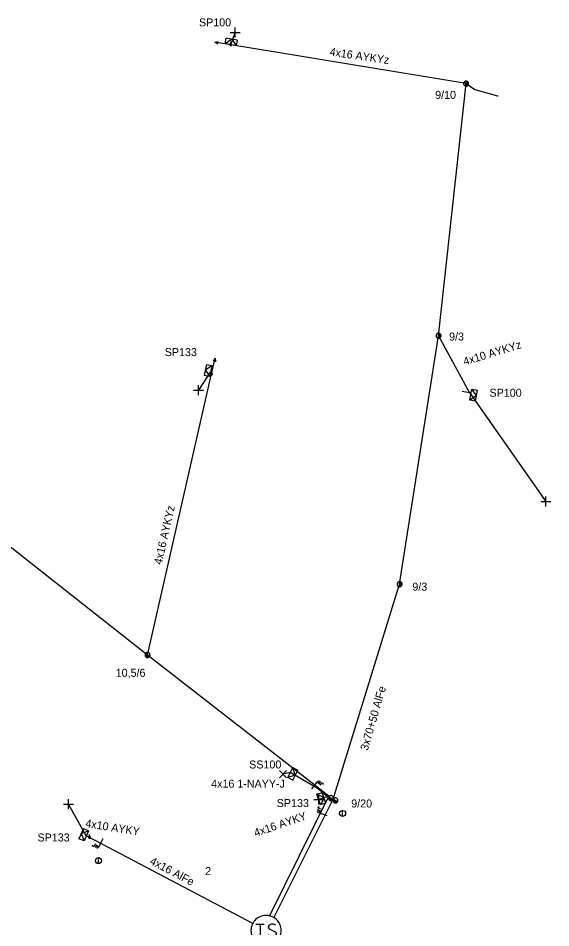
# Model space of a CAD drawing. Extents: x -717562 to -713845, y -1151196 to -1143903.
# Drawn here: x -717097.5 to -717030.9, y -1144017.1 to -1143903.4 of the extents above; entities that cross this region are included whole.
import ezdxf

# ---------------------------------------------------------------- set-up
doc = ezdxf.new("R2010")
doc.units = 0
for name, color, linetype in [('Vrstva 1', 7, 'Continuous'), ('Vrstva 10', 7, 'Continuous'), ('Vrstva 12', 7, 'Continuous'), ('Vrstva 13', 7, 'Continuous'), ('Vrstva 15', 7, 'Continuous'), ('Vrstva 18', 7, 'Continuous'), ('Vrstva 2', 7, 'Continuous'), ('Vrstva 25', 7, 'Continuous'), ('Vrstva 27', 7, 'Continuous'), ('Vrstva 31', 7, 'Continuous'), ('Vrstva 33', 7, 'Continuous'), ('Vrstva 34', 7, 'Continuous'), ('Vrstva 36', 7, 'Continuous'), ('Vrstva 52', 7, 'Continuous'), ('Vrstva 54', 7, 'Continuous'), ('Vrstva 55', 7, 'Continuous'), ('Vrstva 59', 7, 'Continuous'), ('Vrstva 6', 7, 'Continuous'), ('Vrstva 9', 7, 'Continuous')]:
    doc.layers.add(name, color=color, linetype=linetype)

# ---------------------------------------------------------------- blocks, each defined once
blk = doc.blocks.new('NN440')
at = {"layer": 'Vrstva 2'}
for points in [[(0.63, 0), (0.63, 0.06), (0.62, 0.13), (0.6, 0.19), (0.58, 0.25), (0.55, 0.31), (0.51, 0.37), (0.47, 0.42), (0.42, 0.46), (0.37, 0.51), (0.32, 0.54), (0.26, 0.57), (0.2, 0.59), (0.13, 0.61), (0.07, 0.62), (0, 0.63), (-0.06, 0.62), (-0.13, 0.61), (-0.19, 0.59), (-0.26, 0.57), (-0.31, 0.54), (-0.37, 0.51), (-0.42, 0.46), (-0.47, 0.42), (-0.51, 0.37), (-0.54, 0.31), (-0.57, 0.25), (-0.6, 0.19), (-0.62, 0.13), (-0.63, 0.06), (-0.63, 0), (-0.63, -0.07), (-0.62, -0.14), (-0.6, -0.2), (-0.57, -0.26), (-0.54, -0.32), (-0.51, -0.37), (-0.47, -0.43), (-0.42, -0.47), (-0.37, -0.51), (-0.31, -0.55), (-0.26, -0.58), (-0.19, -0.6), (-0.13, -0.62), (-0.06, -0.63), (0, -0.63), (0.07, -0.63), (0.13, -0.62), (0.2, -0.6), (0.26, -0.58), (0.32, -0.55), (0.37, -0.51), (0.42, -0.47), (0.47, -0.43), (0.51, -0.37), (0.55, -0.32), (0.58, -0.26), (0.6, -0.2), (0.62, -0.14), (0.63, -0.07), (0.63, 0)], [(-0.63, 0), (0.63, 0)], [(-0.6, -0.18), (0.57, -0.18)], [(-0.51, -0.32), (0.5, -0.32)], [(-0.37, -0.47), (0.35, -0.47)]]:
    blk.add_lwpolyline(points, dxfattribs=at)
blk = doc.blocks.new('NN450')
at = {"layer": 'Vrstva 2'}
for points in [[(0, 0), (0, 0.07), (-0.01, 0.13), (-0.03, 0.19), (-0.05, 0.25), (-0.08, 0.31), (-0.12, 0.37), (-0.16, 0.42), (-0.21, 0.46), (-0.26, 0.51), (-0.31, 0.54), (-0.37, 0.57), (-0.43, 0.59), (-0.5, 0.61), (-0.56, 0.62), (-0.63, 0.62), (-0.69, 0.62), (-0.75, 0.61), (-0.82, 0.59), (-0.88, 0.57), (-0.94, 0.54), (-0.99, 0.51), (-1.04, 0.46), (-1.09, 0.42), (-1.13, 0.37), (-1.17, 0.31), (-1.2, 0.25), (-1.22, 0.19), (-1.24, 0.13), (-1.25, 0.07), (-1.25, 0), (-1.25, -0.07), (-1.24, -0.13), (-1.22, -0.19), (-1.2, -0.25), (-1.17, -0.31), (-1.13, -0.37), (-1.09, -0.42), (-1.04, -0.46), (-0.99, -0.51), (-0.94, -0.54), (-0.88, -0.57), (-0.82, -0.59), (-0.75, -0.61), (-0.69, -0.62), (-0.62, -0.63), (-0.56, -0.62), (-0.5, -0.61), (-0.43, -0.59), (-0.37, -0.57), (-0.31, -0.54), (-0.26, -0.51), (-0.21, -0.46), (-0.16, -0.42), (-0.12, -0.37), (-0.08, -0.31), (-0.05, -0.25), (-0.03, -0.19), (-0.01, -0.13), (0, -0.07), (0, 0)], [(1.25, 0), (1.25, 0.07), (1.24, 0.13), (1.22, 0.19), (1.2, 0.25), (1.17, 0.31), (1.13, 0.37), (1.09, 0.42), (1.04, 0.46), (0.99, 0.51), (0.94, 0.54), (0.88, 0.57), (0.82, 0.59), (0.75, 0.61), (0.69, 0.62), (0.62, 0.62), (0.56, 0.62), (0.5, 0.61), (0.43, 0.59), (0.37, 0.57), (0.31, 0.54), (0.26, 0.51), (0.21, 0.46), (0.16, 0.42), (0.12, 0.37), (0.08, 0.31), (0.05, 0.25), (0.03, 0.19), (0.01, 0.13), (0, 0.07), (0, 0), (0, -0.07), (0.01, -0.13), (0.03, -0.19), (0.05, -0.25), (0.08, -0.31), (0.12, -0.37), (0.16, -0.42), (0.21, -0.46), (0.26, -0.51), (0.31, -0.54), (0.37, -0.57), (0.43, -0.59), (0.5, -0.61), (0.56, -0.62), (0.63, -0.63), (0.69, -0.62), (0.75, -0.61), (0.82, -0.59), (0.88, -0.57), (0.94, -0.54), (0.99, -0.51), (1.04, -0.46), (1.09, -0.42), (1.13, -0.37), (1.17, -0.31), (1.2, -0.25), (1.22, -0.19), (1.24, -0.13), (1.25, -0.07), (1.25, 0)], [(-1.25, 0), (1.25, 0)], [(-1.23, -0.16), (-0.02, -0.16)], [(-1.16, -0.32), (-0.09, -0.32)], [(-1.03, -0.47), (-0.22, -0.47)], [(0.02, -0.16), (1.23, -0.16)], [(0.09, -0.32), (1.16, -0.32)], [(0.22, -0.47), (1.03, -0.47)]]:
    blk.add_lwpolyline(points, dxfattribs=at)
blk = doc.blocks.new('NN560')
at = {"layer": 'Vrstva 2'}
for points in [[(2, 0), (1.59, 0.14)], [(0, 0), (2, 0)], [(2, 0), (1.59, -0.13)]]:
    blk.add_lwpolyline(points, dxfattribs=at)
blk = doc.blocks.new('NN840')
at = {"layer": 'Vrstva 15'}
for points in [[(0, 0.62), (0, -0.63)], [(-0.75, -0.71), (-0.75, -0.66)], [(-0.73, -0.76), (-0.75, -0.71)], [(-0.66, -0.8), (-0.73, -0.76)], [(-0.63, -0.8), (-0.66, -0.8)], [(-0.56, -0.76), (-0.63, -0.8)], [(-0.54, -0.71), (-0.56, -0.76)], [(-0.54, -0.38), (-0.54, -0.71)], [(-0.33, -0.38), (-0.33, -0.8)], [(-0.33, -0.64), (-0.13, -0.38)], [(-0.26, -0.56), (-0.09, -0.8)]]:
    blk.add_lwpolyline(points, dxfattribs=at)
blk = doc.blocks.new('NN770')
at = {"layer": 'Vrstva 10'}
for p, q in [((0, 0.19), (0, 0.26)), ((0, -0.28), (0, 0.11))]:
    blk.add_line(p, q, dxfattribs=at)
blk.add_circle((0, -0.01), 0.375, dxfattribs=at)
blk = doc.blocks.new('NN800')
at = {"layer": 'Vrstva 1'}
for points in [[(-0.44, 0.44), (0.44, -0.44)], [(-0.44, -0.44), (0.44, 0.44)]]:
    blk.add_lwpolyline(points, dxfattribs=at)
blk = doc.blocks.new('NN630')
at = {"layer": 'Vrstva 9'}
for points in [[(0, -0.7), (-0.7, 0)], [(-0.7, -0.7), (-0.7, 0), (0.7, 0), (0.7, -0.7)], [(-0.7, -0.7), (0.7, -0.7)], [(0, -0.7), (0.7, 0)]]:
    blk.add_lwpolyline(points, dxfattribs=at)
blk = doc.blocks.new('NN500')
at = {"layer": 'Vrstva 2'}
for points in [[(0, -0.24), (0.02, -0.23), (0.05, -0.23), (0.07, -0.22), (0.09, -0.22), (0.12, -0.2), (0.14, -0.19), (0.16, -0.18), (0.17, -0.16), (0.19, -0.14), (0.2, -0.12), (0.21, -0.1), (0.22, -0.07), (0.23, -0.05), (0.23, -0.02), (0.23, 0), (0.23, 0.02), (0.23, 0.05), (0.22, 0.07), (0.21, 0.1), (0.2, 0.12), (0.19, 0.14), (0.17, 0.16), (0.16, 0.17), (0.14, 0.19), (0.12, 0.2), (0.09, 0.21), (0.07, 0.22), (0.05, 0.23), (0.02, 0.23), (0, 0.23), (-0.03, 0.23), (-0.05, 0.23), (-0.07, 0.22), (-0.1, 0.21), (-0.12, 0.2), (-0.14, 0.19), (-0.16, 0.17), (-0.18, 0.16), (-0.19, 0.14), (-0.2, 0.12), (-0.22, 0.1), (-0.22, 0.07), (-0.23, 0.05), (-0.23, 0.02), (-0.24, 0), (-0.23, -0.02), (-0.23, -0.05), (-0.22, -0.07), (-0.22, -0.1), (-0.2, -0.12), (-0.19, -0.14), (-0.18, -0.16), (-0.16, -0.18), (-0.14, -0.19), (-0.12, -0.2), (-0.1, -0.22), (-0.07, -0.22), (-0.05, -0.23), (-0.03, -0.23), (0, -0.24)], [(0, -0.24), (0.02, -0.23), (0.05, -0.23), (0.07, -0.22), (0.09, -0.22), (0.12, -0.2), (0.14, -0.19), (0.16, -0.18), (0.17, -0.16), (0.19, -0.14), (0.2, -0.12), (0.21, -0.1), (0.22, -0.07), (0.23, -0.05), (0.23, -0.02), (0.23, 0), (0.23, 0.02), (0.23, 0.05), (0.22, 0.07), (0.21, 0.1), (0.2, 0.12), (0.19, 0.14), (0.17, 0.16), (0.16, 0.17), (0.14, 0.19), (0.12, 0.2), (0.09, 0.21), (0.07, 0.22), (0.05, 0.23), (0.02, 0.23), (0, 0.23), (-0.03, 0.23), (-0.05, 0.23), (-0.07, 0.22), (-0.1, 0.21), (-0.12, 0.2), (-0.14, 0.19), (-0.16, 0.17), (-0.18, 0.16), (-0.19, 0.14), (-0.2, 0.12), (-0.22, 0.1), (-0.22, 0.07), (-0.23, 0.05), (-0.23, 0.02), (-0.24, 0), (-0.23, -0.02), (-0.23, -0.05), (-0.22, -0.07), (-0.22, -0.1), (-0.2, -0.12), (-0.19, -0.14), (-0.18, -0.16), (-0.16, -0.18), (-0.14, -0.19), (-0.12, -0.2), (-0.1, -0.22), (-0.07, -0.22), (-0.05, -0.23), (-0.03, -0.23), (0, -0.24)], [(0, -0.21), (0.02, -0.2), (0.04, -0.2), (0.06, -0.2), (0.08, -0.19), (0.1, -0.18), (0.12, -0.17), (0.14, -0.15), (0.15, -0.14), (0.16, -0.12), (0.18, -0.1), (0.19, -0.08), (0.19, -0.06), (0.2, -0.04), (0.2, -0.02), (0.2, 0), (0.2, 0.02), (0.2, 0.04), (0.19, 0.06), (0.19, 0.08), (0.18, 0.1), (0.16, 0.12), (0.15, 0.14), (0.14, 0.15), (0.12, 0.17), (0.1, 0.18), (0.08, 0.19), (0.06, 0.19), (0.04, 0.2), (0.02, 0.2), (0, 0.2), (-0.02, 0.2), (-0.04, 0.2), (-0.06, 0.19), (-0.08, 0.19), (-0.1, 0.18), (-0.12, 0.17), (-0.14, 0.15), (-0.15, 0.14), (-0.17, 0.12), (-0.18, 0.1), (-0.19, 0.08), (-0.2, 0.06), (-0.2, 0.04), (-0.21, 0.02), (-0.21, 0), (-0.21, -0.02), (-0.2, -0.04), (-0.2, -0.06), (-0.19, -0.08), (-0.18, -0.1), (-0.17, -0.12), (-0.15, -0.14), (-0.14, -0.15), (-0.12, -0.17), (-0.1, -0.18), (-0.08, -0.19), (-0.06, -0.2), (-0.04, -0.2), (-0.02, -0.2), (0, -0.21)], [(0, -0.18), (0.02, -0.18), (0.04, -0.17), (0.05, -0.17), (0.07, -0.16), (0.09, -0.15), (0.1, -0.14), (0.12, -0.13), (0.13, -0.12), (0.14, -0.1), (0.15, -0.09), (0.16, -0.07), (0.17, -0.05), (0.17, -0.04), (0.17, -0.02), (0.17, 0), (0.17, 0.02), (0.17, 0.04), (0.17, 0.05), (0.16, 0.07), (0.15, 0.09), (0.14, 0.1), (0.13, 0.12), (0.12, 0.13), (0.1, 0.14), (0.09, 0.15), (0.07, 0.16), (0.05, 0.17), (0.04, 0.17), (0.02, 0.17), (0, 0.18), (-0.02, 0.17), (-0.04, 0.17), (-0.06, 0.17), (-0.07, 0.16), (-0.09, 0.15), (-0.1, 0.14), (-0.12, 0.13), (-0.13, 0.12), (-0.14, 0.1), (-0.15, 0.09), (-0.16, 0.07), (-0.17, 0.05), (-0.17, 0.04), (-0.18, 0.02), (-0.18, 0), (-0.18, -0.02), (-0.17, -0.04), (-0.17, -0.05), (-0.16, -0.07), (-0.15, -0.09), (-0.14, -0.1), (-0.13, -0.12), (-0.12, -0.13), (-0.1, -0.14), (-0.09, -0.15), (-0.07, -0.16), (-0.06, -0.17), (-0.04, -0.17), (-0.02, -0.18), (0, -0.18)], [(0, -0.15), (0.01, -0.15), (0.03, -0.14), (0.04, -0.14), (0.06, -0.13), (0.07, -0.13), (0.08, -0.12), (0.1, -0.11), (0.11, -0.1), (0.12, -0.09), (0.13, -0.07), (0.13, -0.06), (0.14, -0.05), (0.14, -0.03), (0.14, -0.02), (0.14, 0), (0.14, 0.01), (0.14, 0.03), (0.14, 0.04), (0.13, 0.06), (0.13, 0.07), (0.12, 0.09), (0.11, 0.1), (0.1, 0.11), (0.08, 0.12), (0.07, 0.13), (0.06, 0.13), (0.04, 0.14), (0.03, 0.14), (0.01, 0.14), (0, 0.15), (-0.02, 0.14), (-0.03, 0.14), (-0.05, 0.14), (-0.06, 0.13), (-0.07, 0.13), (-0.09, 0.12), (-0.1, 0.11), (-0.11, 0.1), (-0.12, 0.09), (-0.13, 0.07), (-0.13, 0.06), (-0.14, 0.04), (-0.14, 0.03), (-0.15, 0.01), (-0.15, 0), (-0.15, -0.02), (-0.14, -0.03), (-0.14, -0.05), (-0.13, -0.06), (-0.13, -0.07), (-0.12, -0.09), (-0.11, -0.1), (-0.1, -0.11), (-0.09, -0.12), (-0.07, -0.13), (-0.06, -0.13), (-0.05, -0.14), (-0.03, -0.14), (-0.02, -0.15), (0, -0.15)], [(0, -0.12), (0.01, -0.12), (0.02, -0.11), (0.03, -0.11), (0.05, -0.11), (0.06, -0.1), (0.07, -0.09), (0.08, -0.09), (0.09, -0.08), (0.09, -0.07), (0.1, -0.06), (0.11, -0.05), (0.11, -0.04), (0.11, -0.02), (0.11, -0.01), (0.12, 0), (0.11, 0.01), (0.11, 0.02), (0.11, 0.04), (0.11, 0.05), (0.1, 0.06), (0.09, 0.07), (0.09, 0.08), (0.08, 0.09), (0.07, 0.09), (0.06, 0.1), (0.05, 0.11), (0.03, 0.11), (0.02, 0.11), (0.01, 0.12), (0, 0.12), (-0.01, 0.12), (-0.03, 0.11), (-0.04, 0.11), (-0.05, 0.11), (-0.06, 0.1), (-0.07, 0.09), (-0.08, 0.09), (-0.09, 0.08), (-0.1, 0.07), (-0.1, 0.06), (-0.11, 0.05), (-0.11, 0.04), (-0.12, 0.02), (-0.12, 0.01), (-0.12, 0), (-0.12, -0.01), (-0.12, -0.02), (-0.11, -0.04), (-0.11, -0.05), (-0.1, -0.06), (-0.1, -0.07), (-0.09, -0.08), (-0.08, -0.09), (-0.07, -0.09), (-0.06, -0.1), (-0.05, -0.11), (-0.04, -0.11), (-0.03, -0.11), (-0.01, -0.12), (0, -0.12)], [(0, -0.09), (0.01, -0.09), (0.02, -0.09), (0.03, -0.08), (0.03, -0.08), (0.04, -0.08), (0.05, -0.07), (0.06, -0.07), (0.06, -0.06), (0.07, -0.05), (0.07, -0.04), (0.08, -0.04), (0.08, -0.03), (0.08, -0.02), (0.09, -0.01), (0.09, 0), (0.09, 0.01), (0.08, 0.02), (0.08, 0.03), (0.08, 0.03), (0.07, 0.04), (0.07, 0.05), (0.06, 0.06), (0.06, 0.06), (0.05, 0.07), (0.04, 0.07), (0.03, 0.08), (0.03, 0.08), (0.02, 0.08), (0.01, 0.09), (0, 0.09), (-0.01, 0.09), (-0.02, 0.08), (-0.03, 0.08), (-0.04, 0.08), (-0.04, 0.07), (-0.05, 0.07), (-0.06, 0.06), (-0.07, 0.06), (-0.07, 0.05), (-0.08, 0.04), (-0.08, 0.03), (-0.08, 0.03), (-0.09, 0.02), (-0.09, 0.01), (-0.09, 0), (-0.09, -0.01), (-0.09, -0.02), (-0.08, -0.03), (-0.08, -0.04), (-0.08, -0.04), (-0.07, -0.05), (-0.07, -0.06), (-0.06, -0.07), (-0.05, -0.07), (-0.04, -0.08), (-0.04, -0.08), (-0.03, -0.08), (-0.02, -0.09), (-0.01, -0.09), (0, -0.09)], [(0, -0.06), (0, -0.06), (0.01, -0.06), (0.02, -0.05), (0.02, -0.05), (0.03, -0.05), (0.03, -0.05), (0.04, -0.04), (0.04, -0.04), (0.05, -0.03), (0.05, -0.03), (0.05, -0.02), (0.05, -0.02), (0.05, -0.01), (0.06, -0.01), (0.06, 0), (0.06, 0.01), (0.05, 0.01), (0.05, 0.02), (0.05, 0.02), (0.05, 0.03), (0.05, 0.03), (0.04, 0.04), (0.04, 0.04), (0.03, 0.05), (0.03, 0.05), (0.02, 0.05), (0.02, 0.05), (0.01, 0.06), (0, 0.06), (0, 0.06), (-0.01, 0.06), (-0.01, 0.06), (-0.02, 0.05), (-0.02, 0.05), (-0.03, 0.05), (-0.03, 0.05), (-0.04, 0.04), (-0.04, 0.04), (-0.05, 0.03), (-0.05, 0.03), (-0.05, 0.02), (-0.06, 0.02), (-0.06, 0.01), (-0.06, 0.01), (-0.06, 0), (-0.06, -0.01), (-0.06, -0.01), (-0.06, -0.02), (-0.05, -0.02), (-0.05, -0.03), (-0.05, -0.03), (-0.04, -0.04), (-0.04, -0.04), (-0.03, -0.05), (-0.03, -0.05), (-0.02, -0.05), (-0.02, -0.05), (-0.01, -0.06), (-0.01, -0.06), (0, -0.06)], [(0, -0.03), (0, -0.03), (0, -0.03), (0.01, -0.03), (0.01, -0.03), (0.01, -0.02), (0.02, -0.02), (0.02, -0.02), (0.02, -0.02), (0.02, -0.02), (0.02, -0.01), (0.02, -0.01), (0.03, -0.01), (0.03, -0.01), (0.03, 0), (0.03, 0), (0.03, 0), (0.03, 0.01), (0.03, 0.01), (0.02, 0.01), (0.02, 0.01), (0.02, 0.02), (0.02, 0.02), (0.02, 0.02), (0.02, 0.02), (0.01, 0.02), (0.01, 0.02), (0.01, 0.03), (0, 0.03), (0, 0.03), (0, 0.03), (0, 0.03), (-0.01, 0.03), (-0.01, 0.03), (-0.01, 0.02), (-0.02, 0.02), (-0.02, 0.02), (-0.02, 0.02), (-0.02, 0.02), (-0.02, 0.02), (-0.03, 0.01), (-0.03, 0.01), (-0.03, 0.01), (-0.03, 0.01), (-0.03, 0), (-0.03, 0), (-0.03, 0), (-0.03, -0.01), (-0.03, -0.01), (-0.03, -0.01), (-0.03, -0.01), (-0.02, -0.02), (-0.02, -0.02), (-0.02, -0.02), (-0.02, -0.02), (-0.02, -0.02), (-0.01, -0.03), (-0.01, -0.03), (-0.01, -0.03), (0, -0.03), (0, -0.03)], [(0.23, 0), (0.7, 0)]]:
    blk.add_lwpolyline(points, dxfattribs=at)
blk = doc.blocks.new('NN610')
at = {"layer": 'Vrstva 6'}
for points in [[(1.88, 0), (1.87, 0.2), (1.84, 0.39), (1.79, 0.58), (1.72, 0.77), (1.63, 0.94), (1.52, 1.11), (1.4, 1.26), (1.26, 1.4), (1.1, 1.53), (0.94, 1.63), (0.76, 1.72), (0.58, 1.8), (0.19, 1.88), (0.19, 1.88), (-0.01, 1.89), (-0.21, 1.88), (-0.4, 1.85), (-0.59, 1.8), (-0.78, 1.72), (-0.95, 1.63), (-1.12, 1.53), (-1.27, 1.4), (-1.41, 1.26), (-1.54, 1.11), (-1.64, 0.94), (-1.73, 0.77), (-1.8, 0.58), (-1.86, 0.39), (-1.89, 0.2), (-1.9, 0), (-1.89, -0.2), (-1.86, -0.39), (-1.8, -0.58), (-1.73, -0.77), (-1.64, -0.95), (-1.54, -1.11), (-1.41, -1.27), (-1.27, -1.41), (-1.12, -1.53), (-0.95, -1.64), (-0.78, -1.73), (-0.59, -1.8), (-0.4, -1.85), (-0.21, -1.88), (-0.01, -1.89), (0.19, -1.88), (0.39, -1.85), (0.58, -1.8), (0.76, -1.73), (0.94, -1.64), (1.1, -1.53), (1.26, -1.41), (1.4, -1.27), (1.52, -1.11), (1.63, -0.95), (1.72, -0.77), (1.79, -0.58), (1.84, -0.39), (1.87, -0.2), (1.88, 0)], [(-1.27, 0.78), (-0.26, 0.78)], [(-0.76, 0.78), (-0.76, -0.79)], [(1.19, 0.66), (0.94, 0.78), (0.62, 0.78), (0.37, 0.66), (0.24, 0.47), (0.24, 0.4), (0.37, 0.22), (1.12, -0.16), (1.25, -0.32), (1.25, -0.48), (1.12, -0.67), (0.87, -0.79), (0.62, -0.79), (0.49, -0.73), (0.24, -0.6)]]:
    blk.add_lwpolyline(points, dxfattribs=at)
blk = doc.blocks.new('NN510')
at = {"layer": 'Vrstva 2'}
blk.add_lwpolyline([(0, 0), (0, 0.94)], dxfattribs=at)

msp = doc.modelspace()

# ---------------------------------------------------------------- linework, layer by layer
at = {"layer": 'Vrstva 1'}
for points in [[(-717065.56, -1144015.86), (-717058.14, -1144001.03), (-717049.84, -1143974.15), (-717044.97, -1143943.1), (-717041.53, -1143911.59), (-717041.52, -1143911.2)], [(-717066.1, -1144015.63), (-717058.66, -1144000.63), (-717081.33, -1143983), (-717107.8, -1143962.18)], [(-717068.17, -1144016.55), (-717088.59, -1144005.79)]]:
    msp.add_lwpolyline(points, dxfattribs=at)
at = {"layer": 'Vrstva 52'}
for points in [[(-717041.53, -1143911.59), (-717040.44, -1143912.33), (-717037.59, -1143913.11), (-717037.53, -1143913.11)], [(-717058.14, -1144001.03), (-717058.54, -1144000.96), (-717060.14, -1143999.64), (-717063.31, -1143997.8), (-717063.49, -1143997.7)], [(-717058.66, -1144000.63), (-717059.94, -1144001.07)], [(-717088.59, -1144005.79), (-717088.99, -1144005.6)]]:
    msp.add_lwpolyline(points, dxfattribs=at)
at = {"layer": 'Vrstva 54'}
for points in [[(-717041.53, -1143911.59), (-717070.94, -1143906.72)], [(-717041.53, -1143911.59), (-717041.27, -1143911.32)], [(-717044.97, -1143943.1), (-717041.1, -1143950.22), (-717040.92, -1143950.45)], [(-717081.33, -1143983), (-717073.34, -1143947.87), (-717073.43, -1143947.51)]]:
    msp.add_lwpolyline(points, dxfattribs=at)
at = {"layer": 'Vrstva 59'}
for points in [[(-717070.94, -1143906.72), (-717070.4, -1143905.19)], [(-717073.43, -1143947.51), (-717074.95, -1143949.91)], [(-717040.92, -1143950.45), (-717031.57, -1143963.81)], [(-717063.49, -1143997.7), (-717064.42, -1143997.89)], [(-717088.99, -1144005.6), (-717091.2, -1144001.65)]]:
    msp.add_lwpolyline(points, dxfattribs=at)

# ---------------------------------------------------------------- block references
at = {"layer": 'Vrstva 13'}
for name, p, rotation in [('NN560', (-717070.94, -1143906.72), 170.91262685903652), ('NN560', (-717073.34, -1143947.87), 77.15110783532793), ('NN510', (-717041.1, -1143950.22), 79.99644719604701)]:
    msp.add_blockref(name, p, dxfattribs=dict(at, rotation=rotation))
for name, p, xscale, yscale, rotation in [('NN500', (-717070.94, -1143906.72), 0.5, 0.5, 90), ('NN440', (-717041.53, -1143911.59), 0.5, 0.5, 76.28266944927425), ('NN440', (-717044.97, -1143943.1), 0.5, 0.5000000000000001, 79.86913055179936), ('NN500', (-717073.34, -1143947.87), 0.5, 0.5, 90), ('NN440', (-717049.84, -1143974.15), 0.5, 0.5, 80.03277499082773), ('NN440', (-717081.33, -1143983), 0.5, 0.5, -27.186069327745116), ('NN450', (-717058.14, -1144001.03), 0.5000000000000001, 0.5, -27.3557889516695), ('NN500', (-717088.59, -1144005.79), 0.5, 0.5, 90)]:
    msp.add_blockref(name, p, dxfattribs=dict(at, xscale=xscale, yscale=yscale, rotation=rotation))
at = {"layer": 'Vrstva 18'}
for p, rotation in [((-717060.43, -1143999.25), 142.14118652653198), ((-717059.46, -1144002.91), -109.49369725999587), ((-717087.19, -1144006.52), -27.94050001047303)]:
    msp.add_blockref('NN840', p, dxfattribs=dict(at, rotation=rotation))
at = {"layer": 'Vrstva 25'}
msp.add_blockref('NN610', (-717066.51, -1144017.43), dxfattribs=at)
at = {"layer": 'Vrstva 31'}
for p, rotation in [((-717070.94, -1143906.72), 169.88176111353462), ((-717073.43, -1143947.51), -101.36976451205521), ((-717040.92, -1143950.45), 79.99644719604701), ((-717063.49, -1143997.7), 63.43494882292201), ((-717059.94, -1144001.07), 109.24460837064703), ((-717088.99, -1144005.6), -113.46693006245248)]:
    msp.add_blockref('NN630', p, dxfattribs=dict(at, rotation=rotation))
at = {"layer": 'Vrstva 34'}
for p, rotation in [((-717070.4, -1143905.19), 45), ((-717074.95, -1143949.91), 45), ((-717031.57, -1143963.81), 44.99999995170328), ((-717059.94, -1144001.07), 45), ((-717091.2, -1144001.65), 45)]:
    msp.add_blockref('NN800', p, dxfattribs=dict(at, rotation=rotation))
msp.add_blockref('NN800', (-717064.42, -1143997.89), dxfattribs=at)
at = {"layer": 'Vrstva 36'}
for p in [(-717056.96, -1144002.79), (-717087.46, -1144008.69)]:
    msp.add_blockref('NN770', p, dxfattribs=at)

# ---------------------------------------------------------------- texts
at = {"layer": 'Vrstva 12'}
for s, p in [('9/10', (-717045.39, -1143913.49)), ('9/3', (-717043.65, -1143943.7)), ('9/3', (-717048.24, -1143974.96)), ('10,5/6', (-717085.31, -1143985.72)), ('9/20', (-717055.88, -1144002.05))]:
    msp.add_text(s, height=1, dxfattribs=at).set_placement(p)
at = {"layer": 'Vrstva 2'}
for s, rotation, p in [('3x70+50 AlFe', 73.874, (-717053.82, -1143995.02)), ('4x16 AlFe', 332.109, (-717081.15, -1144009.06))]:
    msp.add_text(s, height=1, rotation=rotation, dxfattribs=at).set_placement(p)
at = {"layer": 'Vrstva 27'}
msp.add_text('2', height=1, dxfattribs=at).set_placement((-717074.13, -1144010.5))
at = {"layer": 'Vrstva 33'}
for s, p in [('SP100', (-717074.9, -1143904.43)), ('SP133', (-717079.18, -1143945.64)), ('SP100', (-717038.6, -1143950.72)), ('SS100', (-717068.63, -1143997.18)), ('SP133', (-717065.18, -1144002)), ('SP133', (-717095.08, -1144006.3))]:
    msp.add_text(s, height=1, dxfattribs=at).set_placement(p)
at = {"layer": 'Vrstva 54'}
msp.add_text('4x16 1-NAYY-J', height=1, dxfattribs=at).set_placement((-717073.38, -1143999.58))
for s, rotation, p in [('4x16 AYKY', 18.951, (-717067.84, -1144005.73)), ('4x10 AYKY', 351.045, (-717089.15, -1144004.5))]:
    msp.add_text(s, height=1, rotation=rotation, dxfattribs=at).set_placement(p)
at = {"layer": 'Vrstva 55'}
for s, rotation, p in [('4x16 AYKYz', 351.717, (-717058.63, -1143908.07)), ('4x10 AYKYz', 16.957, (-717041.71, -1143946.81)), ('4x16 AYKYz', 77.236, (-717079.57, -1143971.76))]:
    msp.add_text(s, height=1, rotation=rotation, dxfattribs=at).set_placement(p)

doc.saveas('drawing.dxf')
